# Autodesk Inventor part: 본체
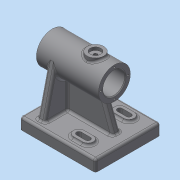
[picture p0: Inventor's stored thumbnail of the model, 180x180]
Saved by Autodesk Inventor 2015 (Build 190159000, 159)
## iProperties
Created: 2026-09
Part Number: 본체
Material: 일반
Document SubType Name: Modeling
Designer: SCD-A06
Density: 1 g/cm^3
Appearance: 기본값
Author: SCD-A06
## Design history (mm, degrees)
sketch "스케치1"
  geometry: L1 (-50, -43)-(50, -43); L2 (50, -43)-(50, 43); L3 (50, 43)-(-50, 43); L4 (-50, 43)-(-50, -43); L5 (-50, -43)-(50, 43); L6 (50, -43)-(-50, 43); 1 further point
  constraints: 12 end point, 2 midpoint, 2 parallel, 1 horizontal, 1 perpendicular
  dimensions: "d0" = 100 distance of L2.end L3.end; "d1" = 86 distance of L1.end L2.end
extrude "돌출1" new body sketch "스케치1" distance "d2" = 15; taper "d3" = 0 deg
node "작업 평면1"
sketch "스케치2"
  geometry: L1 (50, 21)-(-32, 21); L2 (-32, 21)-(-32, 0); L3 (-32, 0)-(50, 0); L4 (50, 0)-(50, 21); L5 (50, 43)-(50, -43) reference; L6 (-50, -43)-(-50, 43) reference; 3 further points
  constraints: 8 end point, 2 midpoint, 2 parallel, 1 coincident, 1 collinear, 1 horizontal, 1 perpendicular, 1 point on line
  dimensions: "d5" = 82 distance of L1.start L1.end; "d7" = 42 diameter of L1 L3
revolve "회전1" sketch "스케치2" stored, may be unused: angle "d8" = 90 deg
sketch "스케치4"
  geometry: L1 (-50, -43)-(50, -43) reference; L2 (-50, 43)-(-50, -43) reference; L3 (-35, -35)-(-25, -35); L4 (-25, -35)-(-25, 35); L5 (-25, 35)-(-35, 35); L6 (-35, 35)-(-35, -35); 3 further points
  constraints: 8 end point, 2 midpoint, 2 parallel, 1 horizontal, 1 horizontal alignment, 1 perpendicular
  dimensions: "d9" = 10 distance of L3.start L3.end; "d10" = 15 distance between parallel lines of L6 L2; "d11" = 8 distance between parallel lines of L3 L1
extrude "돌출2" join sketch "스케치4" distance "d14" = 50; taper "d15" = 0 deg
sketch "스케치6"
  geometry: L1 (50, 70)-(50, 54.799) reference; L2 (0, 70)-(50, 70) reference; L3 (50, 15.201)-(50, 0) reference; L4 (0, 70)-(61.814, 55.441); L5 (0, 70)-(61.814, 70); L6 (61.814, 70)-(61.814, 55.441); L7 (50, 58.223)-(50, 54.799); A1 r 21 centre (57, 35) between (50, 15.201) and (50, 54.799) reference; A2 r 21 centre (57, 35) between (61.814, 55.441) and (50, 54.799); 1 further point
  constraints: 9 end point, 4 point on line, 3 point on circle, 1 centre point, 1 coincident, 1 collinear, 1 concentric, 1 perpendicular, 1 tangent
extrude "돌출3" cut sketch "스케치6" distance "d16" = 50; taper "d17" = 0 deg
extrude "돌출4" join sketch "스케치6" distance "d18" = 10; taper "d19" = 0 deg
sketch "스케치9"
  geometry: L1 (50, 15)-(-50, 15) reference; L2 (-35, 15)-(-28.472, 32.936); L3 (-50, 0)-(-50, 15) reference; 1 further point
  constraints: 2 end point, 1 point on line
  dimensions: "d29" = 15 distance from line of L2.start L3; "d30" = 70 deg angle of L1 L2
feature "리브1" sketch "스케치9" dims "d31" = 1, "d32" = 10, "d33" = 0, "d34" = 0, "d35" = 1, "d36" = 1
sketch "스케치11"
  geometry: 1 further point
sketch "스케치12"
  geometry: L1 (-32, 51)-(-32, 93) reference; L2 (30, 72)-(30, 86.5); L3 (30, 86.5)-(-32, 86.5); L4 (-32, 86.5)-(-32, 72); L5 (50, 72)-(50, 84.5); L6 (50, 84.5)-(30, 84.5); L7 (30, 84.5)-(30, 72); L8 (50, 51)-(50, 93) reference; L9 (-32, 72)-(30, 72); L10 (30, 72)-(50, 72); 1 further point
  constraints: 16 end point, 2 collinear, 2 parallel, 1 horizontal, 1 midpoint
  dimensions: "d41" = 62 distance between parallel lines of L2 L1; "d42" = 29 diameter of L3 L9; "d43" = 25 diameter of L6 L10
revolve "회전2" sketch "스케치12" stored, may be unused: angle "d44" = 90 deg
chamfer "모따기1" distance "d45" = 1; stored, may be unused: second distance "d46" = 2, angle "d47" = 45 deg
node "작업 평면2"
sketch "스케치13"
  geometry: L1 (-32, -21)-(-32, 21) reference; C1 r 11 at (-7, 0); 1 further point
  constraints: 1 centre point, 1 horizontal alignment
  dimensions: "d49" = 22 diameter of C1; "d50" = 25 distance from line of L1 C1.centre
extrude "돌출7" join sketch "스케치13" stored distance "d51" = 10; taper "d52" = 0 deg
hole "구멍1" diameter "d55" = 4.917; stored, may be unused: countersink angle "d59" = 90 deg, drill point angle "d61" = 118 deg; dims "d56" = 12, "d57" = 14, "d58" = 4, "d60" = 17.1, "d100" = 10, "d101" = 10
sketch "스케치14"
  geometry: C1 r 15.5 at (0, 0) reference; A1 r 18 centre (0, 0) between (-18, 0) and (0, 18); 3 further points
  constraints: 4 point on circle, 1 centre point, 1 coincident
  dimensions: "d62" = 36 diameter of A1
hole "구멍2" sketch "스케치14" at (-18, 0), (0, 18), (18, 0), (0, -18) diameter "d63" = 2.459; stored, may be unused: countersink angle "d67" = 82 deg, drill point angle "d69" = 118 deg; dims "d64" = 8, "d65" = 3.023, "d66" = 4, "d68" = 10
sketch "스케치15"
  geometry: C1 r 13.5 at (0, 0) reference; A1 r 18 centre (0, 0) between (18, 0) and (0, 18); 3 further points
  constraints: 4 point on circle, 1 centre point, 1 coincident
  dimensions: "d72" = 36 diameter of A1
hole "구멍3" sketch "스케치15" at (0, -18), (18, 0), (0, 18), (-18, 0) diameter "d73" = 2.459; stored, may be unused: countersink angle "d77" = 82 deg, drill point angle "d79" = 118 deg; dims "d74" = 8, "d75" = 3.023, "d76" = 4, "d78" = 10
sketch "스케치16"
  geometry: L1 (50, -43)-(50, 43) reference; L2 (12, 27)-(24, 27); L3 (12, 20)-(24, 20); L4 (24, 34)-(12, 34); L5 (24, -27)-(12, -27); L6 (24, -34)-(12, -34); L7 (12, -20)-(24, -20); L8 (24, 30.3)-(12, 30.3); L9 (12, 23.7)-(24, 23.7); L10 (24, -23.7)-(12, -23.7); L11 (12, -30.3)-(24, -30.3); A1 r 7 centre (12, 27) between (12, 34) and (12, 20); A2 r 7 centre (24, 27) between (24, 20) and (24, 34); A3 r 7 centre (24, -27) between (24, -34) and (24, -20); A4 r 7 centre (12, -27) between (12, -20) and (12, -34); A5 r 3.3 centre (12, 27) between (12, 30.3) and (12, 23.7); A6 r 3.3 centre (24, 27) between (24, 23.7) and (24, 30.3); A7 r 3.3 centre (12, -27) between (12, -23.7) and (12, -30.3); A8 r 3.3 centre (24, -27) between (24, -30.3) and (24, -23.7); 3 further points
  constraints: 24 end point, 16 point on circle, 8 centre point, 8 tangent, 5 parallel, 2 horizontal, 2 midpoint, 1 vertical alignment, 6 other
  dimensions: "d80" = 12 distance of L4.start L4.end; "d81" = 26 distance from line of L4.start L1; "d82" = 54 distance of L5.start L2.end; "d83" = 27 vertical distance of point (0, 0) point (18, 27) (= 0.5 x d82); "d84" = 7 radius of A2; "d85" = 7 radius of A3; "d86" = 3.7 radial gap between concentric circles of A2 A6; "d87" = 3.7 radial gap between concentric circles of A3 A8
extrude "돌출8" join sketch "스케치16" distance "d88" = 3; taper "d89" = 0 deg
extrude "돌출9" cut sketch "스케치16" stored distance "d90" = 3; taper "d91" = 0 deg
fillet "모깎기1" dims "d92" = 3
fillet "모깎기2" dims "d93" = 3
fillet "모깎기3" dims "d94" = 3
fillet "모깎기4" dims "d95" = 3
fillet "모깎기5" dims "d96" = 3
sketch "스케치17"
  geometry: L1 (0, 80)-(0, 0) reference; 3 further points
  constraints: 1 horizontal alignment, 1 midpoint, 1 other
  dimensions: "d97" = 6 distance of point (6, 40) point (0, 40)
feature "엠보싱1" sketch "스케치17" dims "d0" = 100, "d1" = 86, "d98" = 0.5, "d99" = 0
node "솔리드1"
mirror "대칭1"
other parameters: "d4" = -72, "d48" = -96
